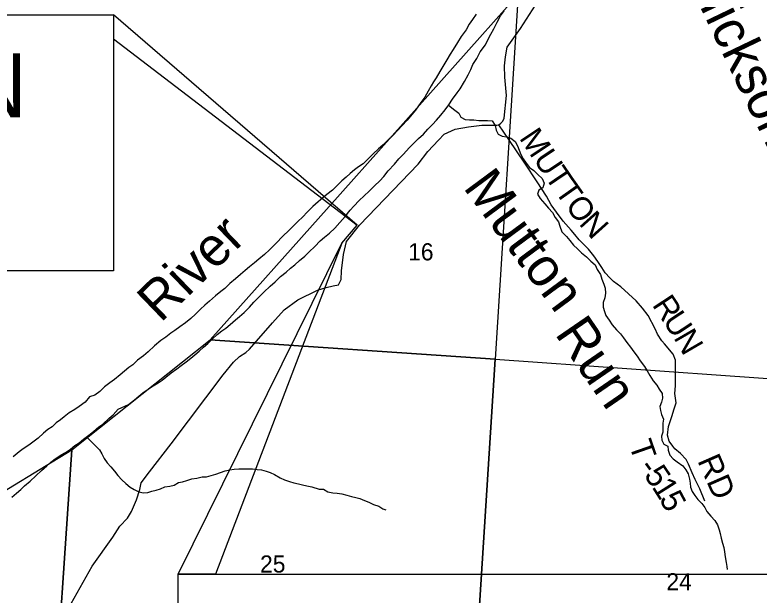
# Model space of a CAD drawing. Extents: x 5.6 to 39.6, y 0.7 to 22.7.
# Drawn here: x 11.039 to 12.858, y 16.574 to 17.991 of the extents above; entities that cross this region are included whole.
import ezdxf

# ---------------------------------------------------------------- set-up
doc = ezdxf.new("R2010")
doc.units = 0
doc.layers.add('Default', color=7, linetype='Continuous')
doc.layers.add('SH_Data', color=7, linetype='Continuous')

msp = doc.modelspace()

# ---------------------------------------------------------------- linework, layer by layer
at = {"layer": 'Default'}
for points in [[(11.169, 16.5404), (11.2275, 16.6448), (11.278, 16.7155), (11.2959, 16.7427), (11.3142, 16.7624), (11.3242, 16.7786), (11.3364, 16.8074), (11.3442, 16.8324), (11.3477, 16.8487), (11.3683, 16.8755), (11.4206, 16.9435), (11.5485, 17.1121), (11.5736, 17.1431), (11.5881, 17.1574), (11.6033, 17.1672), (11.6128, 17.1747), (11.6689, 17.2393), (11.6971, 17.271), (11.7306, 17.2955), (11.7788, 17.3191), (11.7997, 17.3258), (11.8172, 17.3295), (11.8297, 17.3325), (11.8362, 17.345), (11.8371, 17.3662), (11.8422, 17.4061), (11.8496, 17.4383), (11.8813, 17.478), (12.0246, 17.6271), (12.0487, 17.6581), (12.0742, 17.6853), (12.0883, 17.7004), (12.1149, 17.712), (12.1475, 17.7179), (12.1801, 17.7219), (12.2173, 17.7225), (12.2203, 17.7228), (12.2218, 17.7231), (12.2271, 17.7273), (12.2317, 17.7322), (12.2348, 17.7394), (12.2404, 17.7948), (12.2366, 17.8392), (12.2356, 17.867), (12.238, 17.8893), (12.2427, 17.9125), (12.2748, 17.9582), (12.3701, 18.1073)], [(12.1665, 17.9935), (12.1576, 17.9803), (12.1492, 17.9687), (12.1418, 17.9551), (12.1303, 17.9389), (12.1207, 17.9242), (12.1106, 17.9072), (12.1029, 17.8952), (12.0948, 17.882), (12.0879, 17.8695), (12.0779, 17.8529), (12.0686, 17.8379), (12.0621, 17.8277), (12.0563, 17.8179), (12.0493, 17.8051), (12.0409, 17.7907), (12.0339, 17.7806), (12.0259, 17.7693), (12.0182, 17.7591), (12.0059, 17.7441), (11.9982, 17.7343), (11.986, 17.7211), (11.9752, 17.7095), (11.963, 17.6971), (11.9515, 17.6862), (11.9389, 17.6738), (11.9278, 17.6641), (11.9144, 17.6517), (11.9037, 17.6404), (11.8907, 17.6277), (11.8792, 17.6202), (11.8689, 17.6127), (11.8582, 17.6037), (11.8487, 17.5955), (11.8384, 17.5861), (11.8277, 17.5756), (11.815, 17.5636), (11.8017, 17.5527), (11.7917, 17.5445), (11.7803, 17.5351), (11.7669, 17.5231), (11.7527, 17.5088), (11.7439, 17.4991), (11.7301, 17.4856), (11.7179, 17.4739), (11.7068, 17.4634), (11.6957, 17.4525), (11.6758, 17.4323), (11.6617, 17.418), (11.649, 17.4064), (11.6357, 17.3951), (11.625, 17.3857), (11.6127, 17.376), (11.602, 17.367), (11.5906, 17.3573), (11.578, 17.3468), (11.5646, 17.3355), (11.552, 17.3232), (11.5424, 17.3157), (11.5295, 17.3052), (11.5149, 17.2921), (11.5035, 17.2823), (11.4931, 17.2726), (11.4801, 17.2602), (11.4694, 17.2501), (11.4557, 17.2396), (11.4419, 17.2295), (11.4301, 17.2209), (11.4198, 17.2138), (11.4076, 17.2044), (11.3961, 17.1958), (11.3801, 17.1831), (11.3644, 17.1684), (11.353, 17.1591), (11.3388, 17.1478), (11.3274, 17.137), (11.3175, 17.1299), (11.3068, 17.1212), (11.2964, 17.1123), (11.2827, 17.1006), (11.2712, 17.0928)], [(11.3165, 17.0396), (11.3311, 17.0516), (11.3418, 17.0606), (11.3517, 17.0681), (11.362, 17.076), (11.3772, 17.0857), (11.389, 17.0924), (11.3986, 17.0991), (11.4081, 17.107), (11.4211, 17.1171), (11.4348, 17.1268), (11.4452, 17.1347), (11.4574, 17.144), (11.4692, 17.153), (11.4791, 17.1612), (11.4895, 17.1702), (11.5002, 17.18), (11.5105, 17.189), (11.5216, 17.1991), (11.5338, 17.2107), (11.5445, 17.2194), (11.5548, 17.2265), (11.5655, 17.2351), (11.5781, 17.2463), (11.5884, 17.2546), (11.5995, 17.2647), (11.6121, 17.2778), (11.6229, 17.2899), (11.6347, 17.3015), (11.6477, 17.3146), (11.663, 17.3289), (11.6756, 17.3398), (11.6883, 17.3525), (11.7024, 17.363), (11.7127, 17.3727), (11.723, 17.3806), (11.7349, 17.3919), (11.7475, 17.4024), (11.7586, 17.4129), (11.772, 17.426), (11.785, 17.4399), (11.7961, 17.4485), (11.8083, 17.4586), (11.8209, 17.4706), (11.8332, 17.4842), (11.8462, 17.4988), (11.8588, 17.5142), (11.8673, 17.524), (11.8803, 17.5383), (11.8929, 17.5499), (11.9048, 17.5612), (11.9182, 17.5736), (11.9312, 17.5863), (11.9408, 17.5968), (11.9515, 17.6108), (11.9668, 17.6265), (11.9772, 17.6401), (11.989, 17.6513), (12.0025, 17.6671), (12.0136, 17.6776), (12.0254, 17.6897), (12.038, 17.7001), (12.0488, 17.7122), (12.0599, 17.7238), (12.0694, 17.7347), (12.0798, 17.7464), (12.0909, 17.7599), (12.0994, 17.7716), (12.1086, 17.7855), (12.1198, 17.801), (12.1271, 17.8111), (12.1378, 17.8285), (12.1467, 17.8451), (12.1537, 17.8579), (12.1587, 17.8704), (12.168, 17.885), (12.1765, 17.9009), (12.1892, 17.9186), (12.1969, 17.9341), (12.2023, 17.9442), (12.2096, 17.9574), (12.2182, 17.974), (12.2259, 17.9888), (12.2351, 18.0012)], [(12.0987, 17.7707), (12.1145, 17.7589), (12.1246, 17.7511), (12.1293, 17.7415), (12.1398, 17.7363), (12.15, 17.7354), (12.1609, 17.7351), (12.1734, 17.7337), (12.1836, 17.7331), (12.1946, 17.7336), (12.206, 17.733), (12.2133, 17.7211), (12.2153, 17.7096), (12.2204, 17.7), (12.2305, 17.6953), (12.2411, 17.6939), (12.2516, 17.6906), (12.2616, 17.6821), (12.2678, 17.6713), (12.2718, 17.661), (12.2761, 17.6502), (12.2811, 17.6399), (12.2888, 17.6295), (12.2973, 17.6183), (12.3077, 17.6112), (12.3174, 17.6015), (12.3278, 17.5922), (12.3332, 17.5803), (12.3295, 17.5694), (12.3199, 17.5635), (12.3163, 17.5534), (12.3229, 17.543), (12.3347, 17.5302), (12.3432, 17.519), (12.3531, 17.5086), (12.3597, 17.4966), (12.3678, 17.4858), (12.3709, 17.4752), (12.3759, 17.4618), (12.387, 17.4498), (12.3959, 17.4401), (12.4047, 17.4289), (12.4144, 17.4199), (12.424, 17.4102), (12.4363, 17.4009), (12.4467, 17.39), (12.4578, 17.3807), (12.4625, 17.3696), (12.4706, 17.3576), (12.4737, 17.3462), (12.4787, 17.3339), (12.4823, 17.3236), (12.4824, 17.3115), (12.481, 17.3005), (12.4773, 17.2892), (12.4767, 17.2774), (12.4799, 17.2671), (12.4834, 17.2572), (12.4915, 17.246), (12.4992, 17.2348), (12.5095, 17.2221), (12.5192, 17.2124), (12.5265, 17.2024), (12.535, 17.1916), (12.5438, 17.18), (12.5519, 17.1681), (12.56, 17.158), (12.5677, 17.1461), (12.578, 17.133), (12.5842, 17.1218), (12.5915, 17.1107), (12.5995, 17.098), (12.608, 17.0868), (12.6138, 17.0772), (12.6216, 17.0664), (12.6221, 17.0554), (12.6196, 17.0452), (12.6152, 17.035), (12.6168, 17.0251), (12.6196, 17.0152), (12.6243, 17.0041), (12.6233, 16.9939), (12.6231, 16.9836), (12.6232, 16.9726), (12.62, 16.9625), (12.6205, 16.9526), (12.6252, 16.943), (12.635, 16.9382), (12.6362, 16.928), (12.6401, 16.9165), (12.6479, 16.9069), (12.658, 16.9002), (12.6718, 16.8904), (12.6795, 16.88), (12.6846, 16.8704), (12.6881, 16.8578), (12.6897, 16.8475), (12.6907, 16.838), (12.6946, 16.8277), (12.7012, 16.8177), (12.7085, 16.8076)], [(12.7254, 16.8036), (12.7134, 16.834), (12.7018, 16.8565), (12.6947, 16.8732), (12.6858, 16.8938), (12.6801, 16.9056), (12.6658, 16.9201), (12.6523, 16.9312), (12.647, 16.938), (12.638, 16.9502), (12.6347, 16.965), (12.6367, 16.9859), (12.6448, 17.0109), (12.651, 17.0291), (12.6552, 17.0439), (12.6523, 17.0667), (12.6539, 17.0856), (12.6541, 17.1069), (12.6538, 17.1213), (12.6539, 17.1354), (12.6539, 17.1483), (12.6483, 17.1627), (12.6269, 17.1883), (12.6201, 17.1955), (12.6096, 17.2115), (12.604, 17.2245), (12.5872, 17.2572), (12.5736, 17.2755), (12.5578, 17.2934), (12.539, 17.3102), (12.5205, 17.3274), (12.5024, 17.3404), (12.493, 17.3492), (12.4817, 17.3614), (12.4735, 17.3744), (12.4637, 17.3889), (12.4543, 17.403), (12.4408, 17.4194), (12.4314, 17.4293), (12.4186, 17.4419), (12.4081, 17.4548), (12.3987, 17.4659), (12.3791, 17.4873), (12.3629, 17.5094), (12.3502, 17.5273), (12.3386, 17.549), (12.3153, 17.5833), (12.2856, 17.6294), (12.2462, 17.6873), (12.2218, 17.7231)], [(11.2712, 17.0928), (11.2583, 17.0827), (11.2464, 17.0718), (11.2342, 17.0628), (11.2217, 17.0584), (11.2109, 17.0456), (11.1964, 17.0348), (11.1854, 17.0277), (11.1716, 17.0195), (11.1598, 17.0097), (11.1503, 17.0023), (11.14, 16.9948), (11.13, 16.9854), (11.1193, 16.9787), (11.1086, 16.9697), (11.096, 16.9577), (11.0827, 16.948), (11.0727, 16.9405), (11.0594, 16.9319), (11.0491, 16.9244), (11.035, 16.9124)], [(11.0313, 16.8139), (11.0432, 16.8232), (11.0531, 16.8319), (11.0627, 16.8412), (11.076, 16.8525), (11.0898, 16.866), (11.1043, 16.8787), (11.1169, 16.8904), (11.1265, 16.8994), (11.1376, 16.9068), (11.1521, 16.9166), (11.1627, 16.9229), (11.1745, 16.9304), (11.1856, 16.9397), (11.1963, 16.9464), (11.2066, 16.9554), (11.22, 16.9652), (11.2314, 16.9738), (11.244, 16.9854), (11.2539, 16.9917), (11.2696, 17.0068), (11.2792, 17.015), (11.2914, 17.0285), (11.3165, 17.0396)], [(11.2139, 16.9608), (11.2352, 16.9401), (11.2459, 16.9292), (11.2518, 16.9192), (11.2568, 16.9081), (11.2642, 16.8977), (11.2734, 16.8877), (11.2826, 16.8772), (11.2903, 16.8664), (11.3003, 16.856), (11.31, 16.847), (11.3208, 16.8381), (11.3305, 16.8322), (11.3421, 16.8266), (11.3534, 16.8244), (11.364, 16.825), (11.3736, 16.8278), (11.3842, 16.8306), (11.3949, 16.8338), (11.4052, 16.8388), (11.4174, 16.8401), (11.4284, 16.8425), (11.4392, 16.8491), (11.4487, 16.8508), (11.459, 16.854), (11.4712, 16.8579), (11.4837, 16.8602), (11.4971, 16.863), (11.5073, 16.8631), (11.5187, 16.8663), (11.5305, 16.8698), (11.5416, 16.8741), (11.5531, 16.8777), (11.5641, 16.8801), (11.5747, 16.8821), (11.5861, 16.8826), (11.5971, 16.8827), (11.6107, 16.8824), (11.6202, 16.8826), (11.6315, 16.8808), (11.6417, 16.8799), (11.653, 16.8773), (11.6628, 16.8741), (11.6733, 16.8689), (11.6875, 16.861), (11.6984, 16.8555), (11.7104, 16.8514), (11.7209, 16.8489), (11.7326, 16.8464), (11.7424, 16.8435), (11.7526, 16.8414), (11.765, 16.8388), (11.7831, 16.8327), (11.7933, 16.8329), (11.8042, 16.8269), (11.8166, 16.8244), (11.8268, 16.823), (11.8385, 16.8216), (11.8505, 16.8183), (11.8618, 16.8154), (11.8724, 16.8129), (11.8822, 16.81), (11.8938, 16.8056), (11.9043, 16.8016), (11.9159, 16.796), (11.9283, 16.7916), (11.9384, 16.7849), (11.9459, 16.7825)], [(12.7085, 16.8076), (12.7182, 16.7983), (12.7255, 16.7879), (12.7302, 16.7783), (12.7406, 16.7671), (12.7498, 16.7567), (12.7564, 16.7463), (12.761, 16.734), (12.7631, 16.7245), (12.7659, 16.7134), (12.769, 16.7009), (12.7718, 16.6909), (12.7738, 16.6799), (12.7755, 16.6677), (12.7774, 16.654), (12.7795, 16.6445), (12.7804, 16.6365)]]:
    msp.add_lwpolyline(points, dxfattribs=at)
for points in [[(11.8073, 17.5238), (12.2692, 18.0419), (12.2127, 17.1504), (11.5163, 17.1975)], [(11.5163, 17.1975), (12.2127, 17.1504), (12.1494, 16.1525), (11.1299, 16.2192), (11.1778, 16.9289)], [(12.2127, 17.1504), (13.1788, 17.0823), (13.1121, 16.0885), (12.1494, 16.1525)], [(11.1778, 16.9289), (11.1299, 16.2192), (10.5154, 16.2914), (10.5184, 16.2529), (10.169, 16.28), (10.1768, 16.3696), (10.1925, 16.3816), (10.2261, 16.3983), (10.5161, 16.5272), (10.8674, 16.7406)]]:
    msp.add_lwpolyline(points, close=True, dxfattribs=at)
at = {"layer": 'SH_Data'}
msp.add_line((11.8383, 17.4337), (11.8759, 17.4778), dxfattribs=at)
for points in [[(9.1704, 17.9914), (11.2799, 17.9914), (11.2799, 17.3664), (9.1704, 17.3664)], [(11.8759, 17.4778), (11.2799, 17.9914), (11.2799, 17.9332)], [(11.8383, 17.4337), (11.5292, 16.6256), (11.4381, 16.6256)], [(11.4381, 16.6256), (13.5787, 16.6256), (13.5787, 16.0006), (11.4381, 16.0006)]]:
    msp.add_lwpolyline(points, close=True, dxfattribs=at)

# ---------------------------------------------------------------- texts
at = {"layer": 'Default'}
for s, height, rotation, p in [('Hickson', 0.09471, 295.6089, (12.686, 18.0681)), ('M', 0.0568, 303.6098, (12.2704, 17.6907)), ('U', 0.0568, 303.6231, (12.3046, 17.6393)), ('Mutton', 0.0947, 306.477, (12.133, 17.5701)), ('T', 0.0568, 304.0803, (12.3325, 17.5972)), ('T', 0.0568, 305.2554, (12.3571, 17.561)), ('O', 0.0568, 306.6521, (12.3825, 17.5251)), ('N', 0.0568, 311.9258, (12.4159, 17.4805)), ('River', 0.09471, 43.9767, (11.395, 17.2378)), ('16', 0.04182, 0, (12.0002, 17.3919)), ('R', 0.0568, 303.3848, (12.5954, 17.2832)), ('U', 0.0568, 303.3627, (12.6211, 17.2442)), ('Run', 0.09471, 304.4804, (12.3572, 17.2129)), ('N', 0.0568, 300.1497, (12.6481, 17.2032)), ('T', 0.0568, 289.1871, (12.5394, 16.942)), ('RD', 0.05682, 293.7127, (12.7067, 16.9028)), ('-', 0.0568, 305.9646, (12.5618, 16.8858)), ('5', 0.0568, 304.2212, (12.5752, 16.8673)), ('1', 0.0568, 302.4025, (12.5946, 16.8388)), ('5', 0.0568, 298.2292, (12.6128, 16.8102)), ('25', 0.04182, 0, (11.6382, 16.6294)), ('24', 0.04182, 0, (12.6315, 16.586))]:
    msp.add_text(s, height=height, rotation=rotation, dxfattribs=at).set_placement(p)
at = {"layer": 'SH_Data'}
msp.add_text('END ACQUISITION', height=0.156, rotation=360, dxfattribs=at).set_placement((9.2143, 17.7414))

doc.saveas('drawing.dxf')
